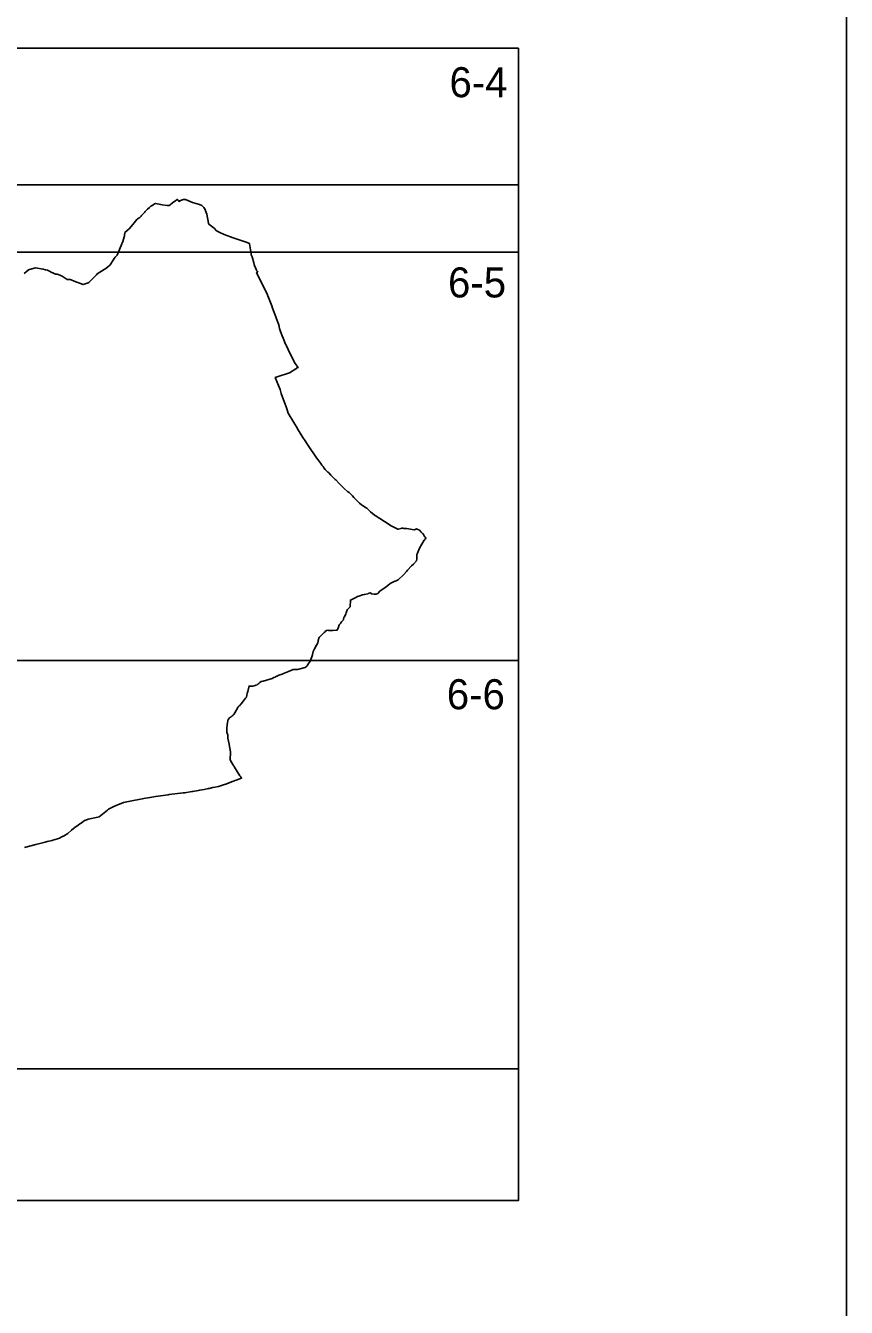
# Model space of a CAD drawing. Extents: x -449577 to -436680, y -1132317 to -1125726.
# Drawn here: x -441550 to -441298.7, y -1130335.5 to -1129943.1 of the extents above; entities that cross this region are included whole.
import ezdxf

# ---------------------------------------------------------------- set-up
doc = ezdxf.new("R2010")
doc.units = 0
for name, color, linetype in [('Vrstva 1', 7, 'Continuous'), ('Vrstva 10', 7, 'Continuous'), ('Vrstva 4', 7, 'Continuous')]:
    doc.layers.add(name, color=color, linetype=linetype)

msp = doc.modelspace()

# ---------------------------------------------------------------- linework, layer by layer
at = {"layer": 'Vrstva 1'}
msp.add_lwpolyline([(-442783.68, -1129648.53), (-442783.68, -1130698.53), (-441298.68, -1130698.53), (-441298.68, -1129648.53)], close=True, dxfattribs=at)
msp.add_lwpolyline([(-441550.39, -1130194.65), (-441546.85, -1130193.78), (-441544.08, -1130193.11), (-441543.41, -1130192.9), (-441541.92, -1130192.54), (-441541.71, -1130192.48), (-441540.28, -1130192.09), (-441539.68, -1130191.83), (-441539.46, -1130191.73), (-441539.3, -1130191.67), (-441538.48, -1130191.22), (-441538.42, -1130191.18), (-441537.11, -1130190.4), (-441535.96, -1130189.35), (-441535.31, -1130188.85), (-441535.18, -1130188.74), (-441535.16, -1130188.73), (-441535, -1130188.6), (-441534.85, -1130188.5), (-441534.05, -1130187.94), (-441533.99, -1130187.9), (-441533.92, -1130187.85), (-441533.41, -1130187.5), (-441533.04, -1130187.24), (-441532.38, -1130186.78), (-441531.79, -1130186.37), (-441531.63, -1130186.4), (-441531.62, -1130186.4), (-441531.6, -1130186.38), (-441530.87, -1130185.99), (-441527.91, -1130185.41), (-441527.49, -1130185.26), (-441525.46, -1130183.63), (-441524.99, -1130183.29), (-441524.96, -1130183.27), (-441524.6, -1130183.01), (-441524.42, -1130182.89), (-441523.03, -1130182.19), (-441521.62, -1130181.55), (-441521.32, -1130181.4), (-441520.06, -1130180.94), (-441519.06, -1130180.69), (-441513.35, -1130179.63), (-441511.93, -1130179.37), (-441510.22, -1130179.12), (-441506.35, -1130178.55), (-441506.11, -1130178.52), (-441501.81, -1130178), (-441501.28, -1130177.94), (-441499.13, -1130177.58), (-441498.81, -1130177.53), (-441497.15, -1130177.26), (-441496.75, -1130177.19), (-441495.34, -1130176.9), (-441494.05, -1130176.63), (-441493.84, -1130176.59), (-441492.67, -1130176.36), (-441492, -1130176.23), (-441491.98, -1130176.23), (-441491.07, -1130176.02), (-441491, -1130176), (-441490.35, -1130175.84), (-441490, -1130175.73), (-441489.11, -1130175.44), (-441488.67, -1130175.29), (-441488.02, -1130175.05), (-441487.9, -1130175.01), (-441486.81, -1130174.52), (-441486.81, -1130174.52), (-441486.69, -1130174.48), (-441486.04, -1130174.25), (-441485.95, -1130174.22), (-441485.52, -1130174.06), (-441483.86, -1130173.48), (-441483.88, -1130173.43), (-441483.99, -1130173.26), (-441484.15, -1130173.03), (-441484.37, -1130172.71), (-441486.07, -1130170.07), (-441486.28, -1130169.72), (-441486.45, -1130169.45), (-441486.89, -1130168.74), (-441487.42, -1130167.89), (-441487.26, -1130165.53), (-441487.25, -1130165.44), (-441487.64, -1130163.14), (-441487.64, -1130163.12), (-441487.65, -1130163.1), (-441487.65, -1130163.1), (-441487.65, -1130163.07), (-441488.06, -1130161.24), (-441488.07, -1130161.05), (-441488.13, -1130160.25), (-441488.23, -1130159.97), (-441488.24, -1130159.95), (-441488.35, -1130159.73), (-441488.39, -1130159.65), (-441488.4, -1130159.27), (-441488.43, -1130158.57), (-441488.38, -1130158.08), (-441488.38, -1130158.06), (-441488.29, -1130157.2), (-441488.27, -1130157.09), (-441487.98, -1130155.45), (-441487.9, -1130155.37), (-441487.6, -1130155.03), (-441487.54, -1130154.96), (-441487.28, -1130154.84), (-441487.22, -1130154.78), (-441486.96, -1130154.58), (-441486.73, -1130154.4), (-441486.52, -1130154.24), (-441486.46, -1130154.2), (-441486.38, -1130154.07), (-441486.3, -1130153.95), (-441486.19, -1130153.78), (-441485.97, -1130153.45), (-441485.55, -1130152.8), (-441485.42, -1130152.55), (-441485.41, -1130152.54), (-441485.27, -1130152.25), (-441485.22, -1130152.16), (-441485.04, -1130151.83), (-441484.9, -1130151.68), (-441484.6, -1130151.37), (-441484.43, -1130151.19), (-441484.15, -1130150.84), (-441484.02, -1130150.67), (-441483.33, -1130149.82), (-441482.67, -1130149.01), (-441482.38, -1130148.65), (-441482.14, -1130147.48), (-441482.08, -1130147.25), (-441482.01, -1130146.97), (-441481.69, -1130145.66), (-441481.61, -1130145.38), (-441481.61, -1130145.35), (-441481.59, -1130145.3), (-441481.43, -1130145.29), (-441481.41, -1130145.29), (-441481.17, -1130145.29), (-441480.48, -1130145.27), (-441480.47, -1130145.27), (-441480.44, -1130145.27), (-441479.76, -1130145.09), (-441479.56, -1130145.03), (-441479.14, -1130144.92), (-441479.12, -1130144.91), (-441479.06, -1130144.85), (-441478.76, -1130144.57), (-441478.64, -1130144.49), (-441478.3, -1130144.23), (-441477.88, -1130143.91), (-441477.81, -1130143.89), (-441477.25, -1130143.73), (-441474.55, -1130142.97), (-441473.96, -1130142.7), (-441473.63, -1130142.54), (-441473.58, -1130142.52), (-441473.48, -1130142.47), (-441473.12, -1130142.29), (-441473.07, -1130142.27), (-441473.04, -1130142.25), (-441473.03, -1130142.25), (-441473, -1130142.23), (-441472.69, -1130142.08), (-441472.63, -1130142.04), (-441472.52, -1130141.99), (-441471.44, -1130141.66), (-441471.01, -1130141.48), (-441470.49, -1130141.26), (-441469.48, -1130140.85), (-441468.06, -1130140.22), (-441467.92, -1130140.21), (-441466.79, -1130140.16), (-441464.39, -1130139.6), (-441463.86, -1130139.2), (-441463.79, -1130139.08), (-441463.7, -1130138.9), (-441463.44, -1130138.39), (-441463.09, -1130137.96), (-441463.07, -1130137.93), (-441462.86, -1130137.64), (-441462.75, -1130137.48), (-441462.74, -1130137.47), (-441462.2, -1130135.69), (-441462.19, -1130135.66), (-441461.99, -1130134.71), (-441461.73, -1130134.25), (-441461.54, -1130133.92), (-441460.99, -1130132.8), (-441460.61, -1130132.29), (-441460.58, -1130132.16), (-441460.51, -1130131.86), (-441460.48, -1130131.72), (-441460.42, -1130131.47), (-441460.4, -1130131.37), (-441460.08, -1130130.36), (-441460.07, -1130130.35), (-441459.78, -1130130.07), (-441459.12, -1130129.44), (-441459.07, -1130129.39), (-441458.6, -1130128.91), (-441458.34, -1130128.65), (-441458.24, -1130128.54), (-441457.87, -1130128.22), (-441457.83, -1130128.22), (-441457.82, -1130128.22), (-441457.41, -1130128.21), (-441457.24, -1130128.22), (-441456.61, -1130128.24), (-441455.9, -1130128.24), (-441454.93, -1130128.15), (-441454.9, -1130128.15), (-441454.65, -1130128.12), (-441454.43, -1130127.76), (-441454.38, -1130127.63), (-441454.36, -1130127.58), (-441454.34, -1130127.52), (-441453.98, -1130126.5), (-441453.84, -1130126.33), (-441453.74, -1130126.22), (-441453.7, -1130126.18), (-441453.64, -1130126.1), (-441453.52, -1130125.97), (-441453.25, -1130125.65), (-441453.16, -1130125.55), (-441453.06, -1130125.43), (-441452.72, -1130125.04), (-441452.65, -1130124.65), (-441452.59, -1130124.34), (-441452.52, -1130124.21), (-441451.97, -1130123.29), (-441451.86, -1130122.9), (-441451.67, -1130122.2), (-441451.55, -1130121.91), (-441451.26, -1130121.64), (-441450.71, -1130121.13), (-441450.64, -1130121.07), (-441450.54, -1130118.96), (-441449.52, -1130118.47), (-441449.12, -1130118.26), (-441448.87, -1130118.13), (-441448.58, -1130117.97), (-441448.36, -1130117.89), (-441448.02, -1130117.76), (-441447.97, -1130117.75), (-441446.88, -1130117.34), (-441446.87, -1130117.34), (-441446.38, -1130117.28), (-441446.3, -1130117.26), (-441445.27, -1130117), (-441445.12, -1130116.96), (-441445.03, -1130116.93), (-441444.86, -1130116.88), (-441444.33, -1130116.71), (-441444.33, -1130116.71), (-441444.32, -1130116.72), (-441444.32, -1130116.72), (-441444.29, -1130116.78), (-441444.16, -1130117), (-441443.28, -1130117.1), (-441443.08, -1130117.12), (-441442.72, -1130117.16), (-441442.63, -1130117.12), (-441442.2, -1130116.94), (-441441.55, -1130116.23), (-441439.91, -1130115.07), (-441439.82, -1130115), (-441439.65, -1130114.89), (-441439.14, -1130114.47), (-441438.39, -1130113.87), (-441437.12, -1130113.3), (-441436.5, -1130113.03), (-441435.96, -1130112.79), (-441435.9, -1130112.76), (-441434.25, -1130111.09), (-441433.41, -1130110.2), (-441433.05, -1130109.82), (-441431.86, -1130108.46), (-441431.26, -1130108), (-441431.21, -1130107.96), (-441430.37, -1130106.95), (-441430.17, -1130106.38), (-441430.26, -1130105.05), (-441430.04, -1130104.56), (-441429.4, -1130103.11), (-441427.94, -1130100.63), (-441427.91, -1130100.58), (-441427.91, -1130100.58), (-441427.89, -1130100.55), (-441427.86, -1130100.51), (-441427.71, -1130100.32), (-441427.45, -1130099.98), (-441427.71, -1130099.68), (-441427.85, -1130099.46), (-441428.32, -1130098.72), (-441428.52, -1130098.53), (-441428.67, -1130098.37), (-441428.86, -1130098.17), (-441429.44, -1130097.6), (-441430.29, -1130097.13), (-441430.74, -1130097.31), (-441431.07, -1130097.43), (-441432.82, -1130097.16), (-441433.43, -1130097.07), (-441433.57, -1130097.06), (-441434.16, -1130097.04), (-441434.54, -1130096.99), (-441434.7, -1130096.96), (-441434.74, -1130096.96), (-441434.77, -1130096.95), (-441434.77, -1130096.95), (-441434.8, -1130096.96), (-441434.9, -1130096.99), (-441435.03, -1130097.02), (-441435.93, -1130097.26), (-441436, -1130097.23), (-441438.07, -1130096.19), (-441440.09, -1130094.91), (-441443, -1130093.09), (-441443.16, -1130092.95), (-441443.2, -1130092.92), (-441443.29, -1130092.84), (-441444.43, -1130091.91), (-441445.58, -1130090.86), (-441445.69, -1130090.76), (-441446.9, -1130090), (-441447.18, -1130089.77), (-441447.81, -1130089.27), (-441448.12, -1130089.03), (-441448.62, -1130088.5), (-441449.34, -1130087.74), (-441449.49, -1130087.58), (-441449.95, -1130087.09), (-441450.92, -1130086.06), (-441451.12, -1130085.95), (-441451.12, -1130085.95), (-441451.3, -1130085.86), (-441451.5, -1130085.76), (-441452.33, -1130084.93), (-441452.96, -1130084.3), (-441454.14, -1130083.13), (-441455.07, -1130082.19), (-441455.23, -1130082.04), (-441455.67, -1130081.59), (-441455.91, -1130081.35), (-441456, -1130081.26), (-441456.04, -1130081.22), (-441456.56, -1130080.7), (-441457.2, -1130080.05), (-441457.28, -1130079.97), (-441457.3, -1130079.95), (-441457.45, -1130079.8), (-441458.28, -1130078.96), (-441458.66, -1130078.46), (-441458.94, -1130078.09), (-441459.26, -1130077.66), (-441459.62, -1130077.18), (-441460.57, -1130075.92), (-441460.94, -1130075.38), (-441463.48, -1130071.64), (-441463.65, -1130071.38), (-441464.42, -1130070.19), (-441465.09, -1130069.18), (-441465.93, -1130067.85), (-441466.73, -1130066.58), (-441466.81, -1130066.45), (-441467.9, -1130064.6), (-441469.58, -1130061.75), (-441469.58, -1130061.74), (-441469.58, -1130061.74), (-441469.59, -1130061.74), (-441469.92, -1130060.76), (-441470.37, -1130059.46), (-441470.43, -1130059.26), (-441471.81, -1130055.75), (-441472.1, -1130054.5), (-441473.58, -1130050.82), (-441472.95, -1130050.62), (-441469.23, -1130049.38), (-441467.26, -1130048.16), (-441467.08, -1130048.05), (-441467.02, -1130048.01), (-441466.82, -1130047.89), (-441466.55, -1130047.72), (-441467.47, -1130046.53), (-441468.88, -1130043.75), (-441469.63, -1130042.28), (-441470.16, -1130041.12), (-441470.18, -1130041.08), (-441470.24, -1130040.95), (-441470.25, -1130040.92), (-441470.27, -1130040.89), (-441470.31, -1130040.8), (-441470.64, -1130040.07), (-441470.96, -1130039.28), (-441471.67, -1130037.51), (-441472.08, -1130036.47), (-441472.23, -1130035.84), (-441472.49, -1130034.71), (-441473.23, -1130032.82), (-441473.43, -1130032.22), (-441474.37, -1130029.59), (-441474.64, -1130028.87), (-441475.83, -1130025.78), (-441475.9, -1130025.6), (-441475.93, -1130025.52), (-441479.28, -1130018.71), (-441478.97, -1130018.57), (-441478.95, -1130018.56), (-441479.05, -1130018.39), (-441479.13, -1130018.29), (-441479.3, -1130018.06), (-441479.36, -1130017.98), (-441479.97, -1130016.5), (-441480.02, -1130016.21), (-441480.12, -1130015.75), (-441480.13, -1130015.69), (-441480.64, -1130013.85), (-441480.94, -1130013.22), (-441480.95, -1130013.14), (-441480.99, -1130012.78), (-441481.13, -1130011.69), (-441481.41, -1130009.85), (-441481.47, -1130009.83), (-441481.77, -1130009.73), (-441482.15, -1130009.47), (-441482.16, -1130009.47), (-441486.46, -1130008.06), (-441489.25, -1130007.08), (-441490.56, -1130006.46), (-441491.53, -1130005.9), (-441492.25, -1130005.12), (-441493.93, -1130003.85), (-441493.99, -1130003.55), (-441494.57, -1130000.85), (-441494.72, -1130000.31), (-441494.9, -1129999.8), (-441494.95, -1129999.64), (-441495.2, -1129999.12), (-441495.45, -1129998.81), (-441496.03, -1129998.12), (-441496.78, -1129997.91), (-441498.96, -1129997.25), (-441501.05, -1129996.29), (-441501.67, -1129996.29), (-441502.62, -1129996.66), (-441502.75, -1129996.75), (-441502.82, -1129996.8), (-441502.96, -1129996.9), (-441503, -1129996.93), (-441503.02, -1129996.91), (-441503.23, -1129996.66), (-441503.48, -1129996.38), (-441503.56, -1129996.28), (-441503.65, -1129996.32), (-441504.16, -1129996.71), (-441504.35, -1129996.86), (-441505.02, -1129997.38), (-441505.77, -1129997.94), (-441506.11, -1129998.16), (-441506.7, -1129998.12), (-441508.18, -1129997.97), (-441508.64, -1129997.88), (-441510.23, -1129997.56), (-441510.53, -1129997.67), (-441511.09, -1129998.02), (-441511.64, -1129998.34), (-441512.13, -1129998.8), (-441512.66, -1129999.29), (-441513.06, -1129999.68), (-441513.07, -1129999.69), (-441513.4, -1130000.03), (-441513.53, -1130000.17), (-441514.04, -1130000.72), (-441514.49, -1130001.27), (-441514.65, -1130001.46), (-441515.01, -1130001.89), (-441515.75, -1130002.22), (-441515.77, -1130002.22), (-441515.97, -1130002.47), (-441516.83, -1130003.49), (-441517.21, -1130003.94), (-441518.34, -1130005.3), (-441518.35, -1130005.31), (-441519.59, -1130006.48), (-441519.71, -1130007.32), (-441519.76, -1130007.69), (-441519.8, -1130007.79), (-441520.28, -1130009.14), (-441520.72, -1130010.38), (-441520.75, -1130010.46), (-441521.05, -1130011.15), (-441521.98, -1130013.33), (-441522, -1130013.34), (-441522.57, -1130014.02), (-441522.87, -1130014.37), (-441522.87, -1130014.38), (-441523.21, -1130014.92), (-441524.08, -1130016.31), (-441524.17, -1130016.45), (-441524.34, -1130016.58), (-441524.87, -1130016.97), (-441525.48, -1130017.42), (-441525.48, -1130017.42), (-441526.45, -1130018.05), (-441526.58, -1130018.14), (-441526.76, -1130018.26), (-441528.06, -1130019.12), (-441528.07, -1130019.13), (-441528.33, -1130019.39), (-441528.45, -1130019.51), (-441528.67, -1130019.74), (-441528.95, -1130020.02), (-441529.52, -1130020.59), (-441530.68, -1130021.75), (-441530.88, -1130021.83), (-441532.38, -1130022.4), (-441535.19, -1130021.28), (-441535.19, -1130021.29), (-441535.2, -1130021.31), (-441536.11, -1130020.93), (-441536.42, -1130020.8), (-441536.44, -1130020.8), (-441536.83, -1130020.8), (-441537.31, -1130020.8), (-441538.87, -1130019.81), (-441539.13, -1130019.68), (-441539.42, -1130019.52), (-441539.48, -1130019.49), (-441539.52, -1130019.47), (-441540.06, -1130019.24), (-441540.11, -1130019.24), (-441540.12, -1130019.24), (-441540.27, -1130019.23), (-441540.39, -1130019.22), (-441540.7, -1130019.2), (-441540.72, -1130019.2), (-441540.72, -1130019.2), (-441540.83, -1130019.16), (-441541.07, -1130019.06), (-441541.67, -1130018.81), (-441541.83, -1130018.74), (-441543.35, -1130018.01), (-441543.97, -1130017.83), (-441544.64, -1130017.63), (-441546.96, -1130017.2), (-441546.97, -1130017.2), (-441547.37, -1130017.31), (-441549.11, -1130017.89), (-441549.24, -1130018), (-441550.45, -1130018.96)], dxfattribs=at)
at = {"layer": 'Vrstva 10'}
msp.add_lwpolyline([(-441399.09, -1129991.79), (-441399.09, -1130302.77), (-441731.96, -1130302.77), (-441731.96, -1130137.47), (-441711.59, -1130137.47), (-441711.59, -1130012.47), (-441711.59, -1129991.79), (-441399.09, -1129991.79)], dxfattribs=at)
at = {"layer": 'Vrstva 4'}
msp.add_line((-441711.59, -1129949.97), (-441399.09, -1129949.97), dxfattribs=at)
msp.add_lwpolyline([(-441399.09, -1129949.97), (-441399.09, -1130012.47), (-441555.34, -1130012.47), (-441555.34, -1129949.97)], dxfattribs=at)
for points in [[(-441399.09, -1130012.47), (-441399.09, -1130137.47), (-441555.34, -1130137.47), (-441555.34, -1130012.47)], [(-441399.09, -1130137.47), (-441399.09, -1130262.47), (-441555.34, -1130262.47), (-441555.34, -1130137.47)]]:
    msp.add_lwpolyline(points, close=True, dxfattribs=at)

# ---------------------------------------------------------------- texts
at = {"layer": 'Vrstva 1'}
for s, p in [('6-4', (-441420.22, -1129965.02)), ('6-5', (-441420.67, -1130026.31)), ('6-6', (-441421.04, -1130152.38))]:
    msp.add_text(s, height=9.2, dxfattribs=at).set_placement(p)

doc.saveas('drawing.dxf')
